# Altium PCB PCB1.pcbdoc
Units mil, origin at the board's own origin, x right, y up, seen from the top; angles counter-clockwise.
Board outline 2755.91 x 1968.5 mil, 2 copper layers (Top Layer, Bottom Layer), stack 62.206 mil thick; 33 components, 44 nets, 146 pads, 1 vias.
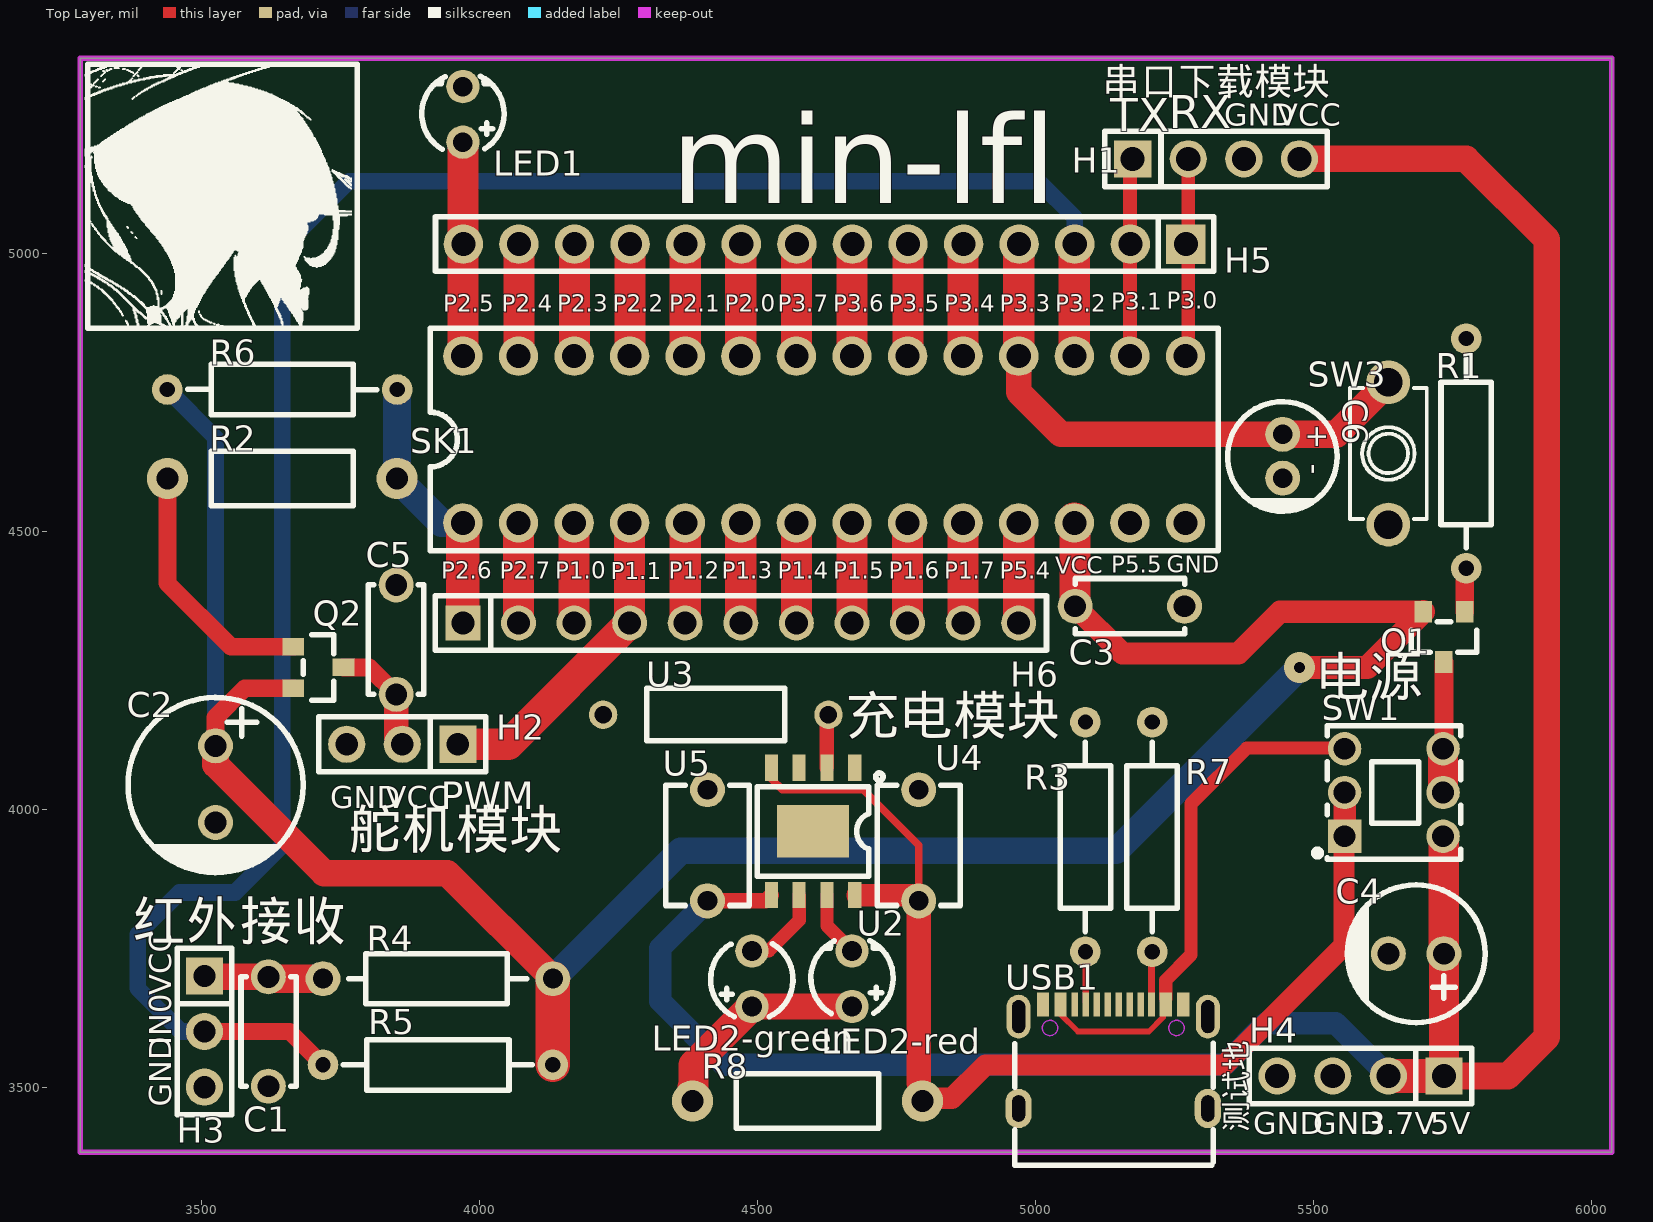
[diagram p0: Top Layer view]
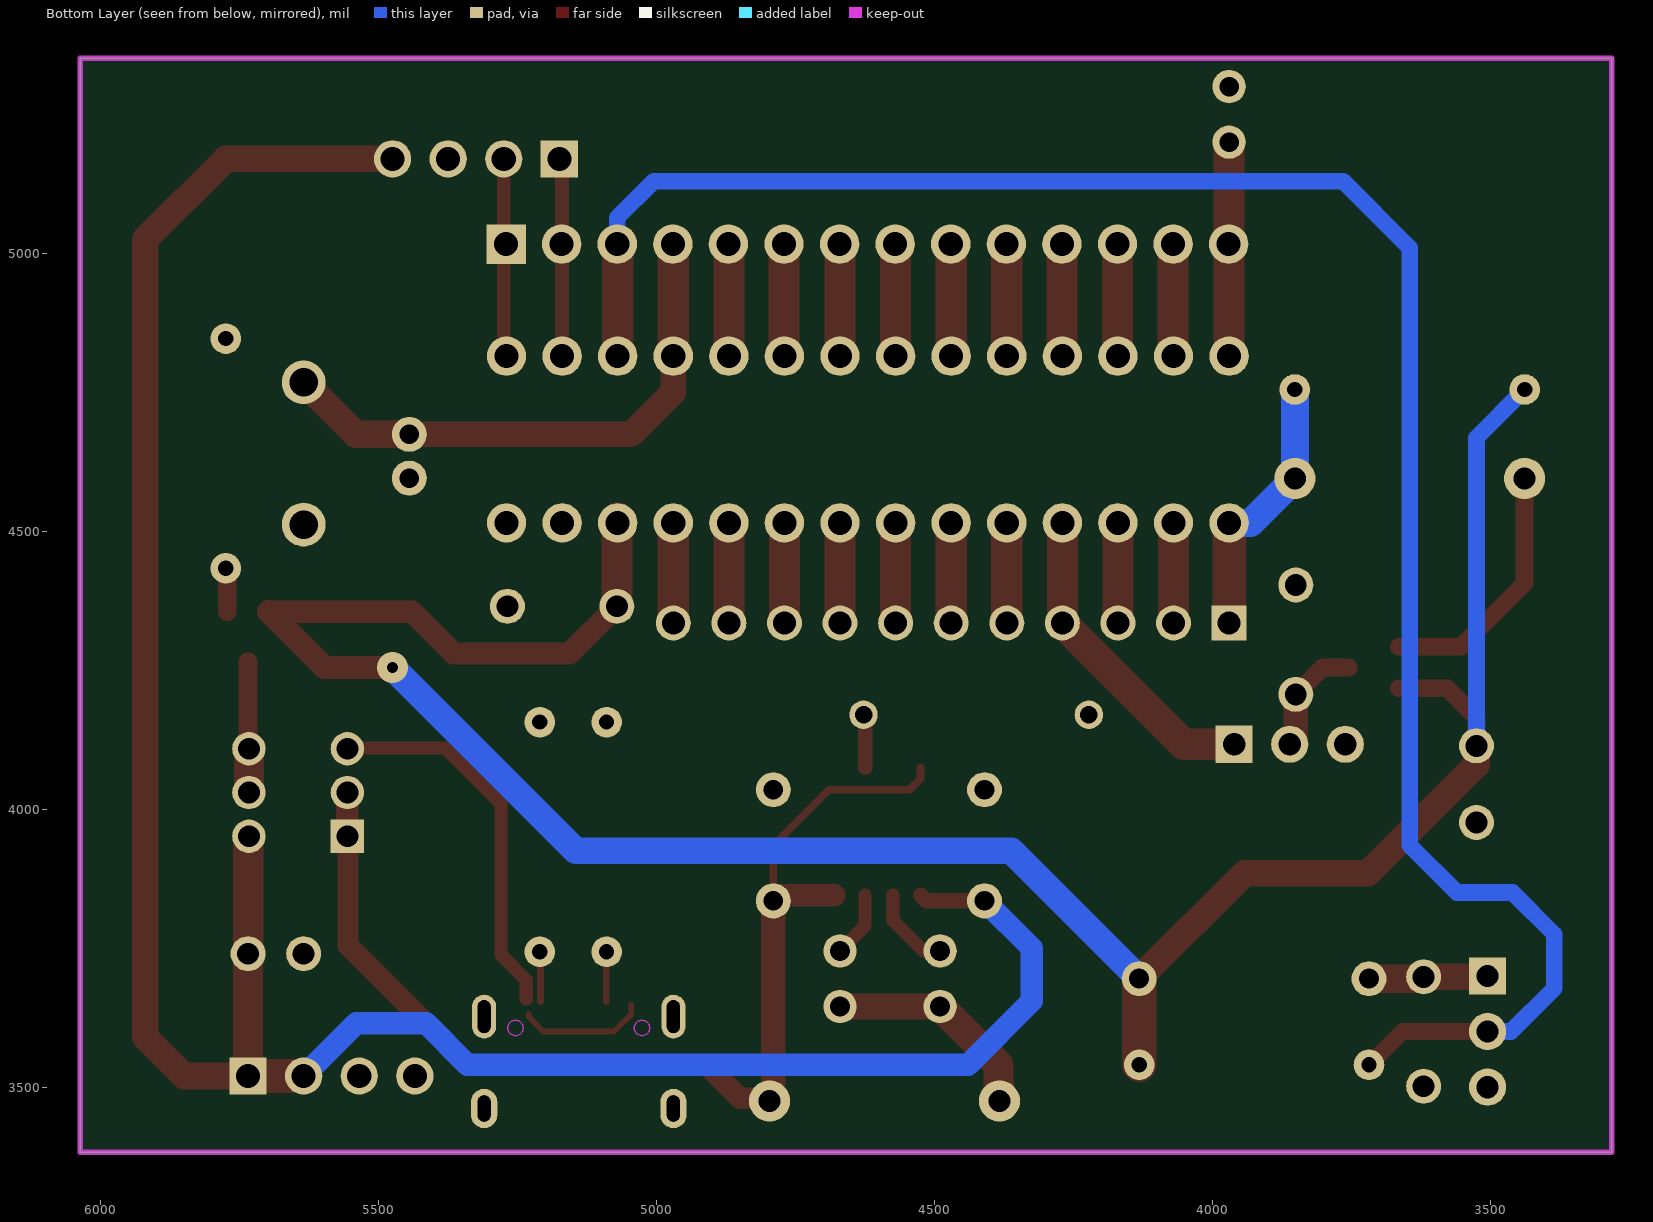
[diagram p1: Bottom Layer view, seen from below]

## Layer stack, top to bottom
Top Solder Mask Layer: solder mask 0.394, Dk 3.3
Top Layer: signal copper 1.379
Dielectric1: surface 59.449, FR4, Dk 4.5
Bottom Layer: signal copper 1.378
Bottom Solder Mask Layer: solder mask 0.394, Dk 3.3

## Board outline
3281.3,3382.8 3281.3,5351.3 6037.2,5351.3 6037.2,3382.8

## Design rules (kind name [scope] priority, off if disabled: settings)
BoardOutlineClearance copperThickness1oz [All] p0: genericclearance=10 ignorepadtopadclearanceinfootprint=FALSE except(0: Arc-SplitContinuation Track-SplitContinuation SMDPad-SplitContinuation THPad-SplitContinuation Via-SplitContinuation Fill-SplitContinuation Poly-SplitContinuation Region-SplitContinuation Text-SplitContinuation)
BoardOutlineClearance copperThickness2oz [All] p0: genericclearance=10 ignorepadtopadclearanceinfootprint=FALSE except(0: Arc-SplitContinuation Track-SplitContinuation SMDPad-SplitContinuation THPad-SplitContinuation Via-SplitContinuation Fill-SplitContinuation Poly-SplitContinuation Region-SplitContinuation Text-SplitContinuation)
BoardOutlineClearance otherClearance [All] p0: genericclearance=10 ignorepadtopadclearanceinfootprint=FALSE except(0: Arc-SplitContinuation Track-SplitContinuation SMDPad-SplitContinuation THPad-SplitContinuation Via-SplitContinuation Fill-SplitContinuation Poly-SplitContinuation Region-SplitContinuation Text-SplitContinuation)
Clearance copperThickness1oz [All] p1: gap=7 ignorepadtopadclearanceinfootprint=FALSE
Clearance copperThickness2oz [All] p1: gap=7 ignorepadtopadclearanceinfootprint=FALSE
Clearance otherClearance [All] p1: gap=7 ignorepadtopadclearanceinfootprint=FALSE
DiffPairsRouting differentialPair [All] p1: maxuncoupledlength=10 minlimit=6 maxlimit=Infinity mostfreqgap=6 toplayer_minwidth=5 toplayer_prefwidth=10 toplayer_maxwidth=100 bottomlayer_minwidth=5 bottomlayer_prefwidth=10 bottomlayer_maxwidth=100
PasteMaskExpansion pasteMaskExpansion [All] p1: expansion=0
PlaneConnect innerPlane [All] p1: planeconnectstyle=Relief reliefexpansion=20 reliefentries=4 reliefconductorwidth=10 reliefairgap=10
PolygonConnect copperRegion [All] p1: connectstyle=Relief reliefentries=4 reliefconductorwidth=10 polygonreliefangle="90 Angle" airgapwidth=10
PolygonConnect copperRegion1 [All] p1: connectstyle=Direct reliefentries=4 reliefconductorwidth=10 polygonreliefangle="90 Angle" airgapwidth=10
RoutingVias viaSize [All] p1: viastyle="Through Hole" holewidth=12.0078 minholewidth=11.811 maxholewidth=248.0314 width=12.0078 minwidth=11.811 maxwidth=248.0314
SolderMaskExpansion solderMaskExpansion [IsVia] p1: useseparateexpansions=TRUE expansion=-1000 expansionbottom=-1000
SolderMaskExpansion solderMaskExpansion [All] p2: useseparateexpansions=TRUE expansion=2 expansionbottom=2
Width copperThickness1oz [All] p1: maxlimit=100 minlimit=5 preferedwidth=10
Width copperThickness2oz [All] p1: maxlimit=100 minlimit=8 preferedwidth=10

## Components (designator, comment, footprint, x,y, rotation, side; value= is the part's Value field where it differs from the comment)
C1 "100nF" CAP-TH_L5.0-W2.5-P5.00-D1.0 3620,3600 r90 top
C2 "470uF" CAP-TH_BD8.0-P3.50-D0.6-FD_1 3525,4045 r270 top
C3 "100nF" CAP-TH_L5.0-W2.5-P5.00-D1.0 5170,4365 r180 top
C4 "47uF" CAP-TH_BD6.3-P2.50-D1.0-FD 5685,3740 r180 top
C5 "100nF" CAP-TH_L5.0-W2.5-P5.00-D1.0 3850,4305 r270 top
C6 "10uF" CAP-TH_BD5.0-P2.00-D0.5-FD-A 5445,4635 r270 top
H1 "PZ254V-11-04P" HDR-TH_4P-P2.54-V-M 5325,5170 r0 top
H2 "PZ254V-11-03P" HDR-TH_3P-P2.54-V-M_PZ254V-11-03P 3860.96,4116.74 r180 top
H3 "PZ254V-11-03P" HDR-TH_3P-P2.54-V-M_PZ254V-11-03P 3505,3600 r270 top
H4 "PZ254V-11-04P" HDR-TH_4P-P2.54-V-M 5585,3520 r180 top
H5 "PZ254-1-14-Z-8.5" HDR-TH_14P-P2.54-V-M 4620.76,5016.73 r180 top
H6 "PZ254V-11-11P" HDR-TH_11P-P2.54-V-M 4470,4335 r0 top
LED1 "XL-302SURD" LED-TH_BD3.8-P2.54-RD 3970,5250 r270 top
LED2-green "XL-302UGD" LED-TH_BD3.8-P2.54-FD_GREEN 4490,3695 r90 top
LED2-red "XL-302SURD" LED-TH_BD3.8-P2.54-RD 4670,3695 r270 top
Q1 "AO3401A" SOT-23_L2.9-W1.3-P1.90-LS2.4-BR 5735,4310 r90 top
Q2 "AO3401A" SOT-23_L2.9-W1.3-P1.90-LS2.4-BR 3710,4255 r180 top
R1 "4.7kΩ" RES-TH_BD2.3-L6.5-P10.50-D0.5 5775,4640 r270 top
R2 "1kΩ" RES-TH_BD2.5-L6.5-P10.50-D0.6 3645,4595 r180 top
R3 "5.1kΩ" RES-TH_BD2.3-L6.5-P10.50-D0.5 5090,3950 r270 top
R4 "100Ω" RES-TH_BD2.2-L6.5-P10.50-D0.6 3925,3695 r180 top
R5 "4.7kΩ" RES-TH_BD2.3-L6.5-P10.50-D0.5 3925,3540 r0 top
R6 "4.7kΩ" RES-TH_BD2.3-L6.5-P10.50-D0.5 3645,4755 r180 top
R7 "5.1kΩ" RES-TH_BD2.3-L6.5-P10.50-D0.5 5210,3950 r270 top
R8 "1kΩ" RES-TH_BD2.5-L6.5-P10.50-D0.6 4590,3475 r0 top
SK1 "IC-28P窄" DIP-28_L36.0-W10.2-P2.54-LS10.2-BL 4620,4665 r0 top
SW1 "5.8 ZSGT" SW-TH_5.8ZSGT 5645,4030 r270 top
SW3 "TC-1101T-C-B-B" KEY-TH_2P-L6.0-W3.5-P6.50 5635,4640 r90 top
U2 "TP4056" ESOP-8_L4.9-W3.9-P1.27-LS6.0-BL-EP 4600,3960 r180 top
U3 "1.2kΩ" RES-TH_BD2.4-L6.3-P10.30-D0.6 4425,4170 r0 top
U4 "10uF" CAP-TH_L5.5-W3.8-P5.08-D0.5 4790,3935 r270 top
U5 "10uF" CAP-TH_L5.5-W3.8-P5.08-D0.5 4410,3935 r270 top
USB1 "TYPE-C 16PIN 2MD(073)" USB-C-SMD_TYPE-C-6PIN-2MD-073 5140,3555 r0 top

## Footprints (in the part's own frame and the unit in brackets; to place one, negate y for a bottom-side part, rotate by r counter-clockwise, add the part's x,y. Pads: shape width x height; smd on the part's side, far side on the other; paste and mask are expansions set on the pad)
CAP-TH_BD5.0-P2.00-D0.5-FD-A [mm]
  round 1.6 hole 0.9 paste+0 mask+0.05: 1(-1,0) 2(1,0)
  silkscreen extent -2.49,-2.52 2.6,2.49
CAP-TH_BD6.3-P2.50-D1.0-FD [mm]
  round 1.6 hole 1: 1(-1.27,0) 2(1.27,0)
  silkscreen extent -3.15,-3.15 3.17,3.15
CAP-TH_BD8.0-P3.50-D0.6-FD_1 [mm]
  round 1.6 hole 1: 1(-1.75,0) 2(1.75,0)
  silkscreen extent -3.96,-4 4.04,4
CAP-TH_L5.0-W2.5-P5.00-D1.0 [mm]
  round 1.6 hole 1: 1(-2.5,0) 2(2.5,0)
  silkscreen extent -2.5,-1.27 2.5,1.25
CAP-TH_L5.5-W3.8-P5.08-D0.5 [mm]
  round 1.6 hole 0.9: 1(-2.54,0) 2(2.54,0)
  silkscreen extent -2.75,-1.9 2.75,1.9
DIP-28_L36.0-W10.2-P2.54-LS10.2-BL [mm]
  round 1.8 hole 1.1: 1(-16.51,-3.81) 2(-16.51,3.81) 3(-13.97,-3.81) 4(-13.97,3.81) 5(-11.43,-3.81) 6(-11.43,3.81) 7(-8.89,-3.81) 8(-8.89,3.81) 9(-6.35,-3.81) 10(-6.35,3.81) 11(-3.81,-3.81) 12(-3.81,3.81) 13(-1.27,-3.81) 14(-1.27,3.81) 15(1.27,-3.81) 16(1.27,3.81) 17(3.81,-3.81) 18(3.81,3.81) 19(6.35,-3.81) 20(6.35,3.81) 21(8.89,-3.81) 22(8.89,3.81) 23(11.43,-3.81) 24(11.43,3.81) 25(13.97,-3.81) 26(13.97,3.81) 27(16.51,-3.81) 28(16.51,3.81)
  silkscreen extent -18,-5.08 18,5.08
ESOP-8_L4.9-W3.9-P1.27-LS6.0-BL-EP [mm]
  rect 0.6x1.2 smd: 1(-1.905,-2.908) 2(-0.635,-2.908) 3(0.635,-2.908) 4(1.905,-2.908) 5(1.905,2.908) 6(0.635,2.908) 7(-0.635,2.908) 8(-1.905,2.908)
  rect 3.3x2.4 smd: 9(0,0)
  silkscreen extent -3.2,-2.67 2.55,2.05
HDR-TH_3P-P2.54-V-M_PZ254V-11-03P [mm]
  rect 1.7x1.7 hole 1.02: 1(-2.54,0)
  round 1.7 hole 1.02: 2(0,0) 3(2.54,0)
  silkscreen extent -3.81,-1.25 3.81,1.25
HDR-TH_4P-P2.54-V-M [mm]
  rect 1.7x1.7 hole 1.1: 1(-3.81,0)
  round 1.7 hole 1.1: 2(-1.27,0) 3(1.27,0) 4(3.81,0)
  silkscreen extent -5.08,-1.27 5.08,1.27
HDR-TH_11P-P2.54-V-M [mm]
  rect 1.6x1.6 hole 1.05: 1(-12.7,0)
  round 1.6 hole 1.05: 2(-10.16,0) 3(-7.62,0) 4(-5.08,0) 5(-2.54,0) 6(0,0) 7(2.54,0) 8(5.08,0) 9(7.62,0) 10(10.16,0) 11(12.7,0)
  silkscreen extent -13.97,-1.25 13.97,1.25
HDR-TH_14P-P2.54-V-M [mm]
  rect 1.8x1.8 hole 1.1: 1(-16.51,0)
  round 1.8 hole 1.1: 2(-13.97,0) 3(-11.43,0) 4(-8.89,0) 5(-6.35,0) 6(-3.81,0) 7(-1.27,0) 8(1.27,0) 9(3.81,0) 10(6.35,0) 11(8.89,0) 12(11.43,0) 13(13.97,0) 14(16.51,0)
  silkscreen extent -17.78,-1.25 17.78,1.25
KEY-TH_2P-L6.0-W3.5-P6.50 [mm]
  round 2 hole 1.3: 1(-3.25,0) 2(3.25,0)
  silkscreen extent -3,-1.75 3,1.75
LED-TH_BD3.8-P2.54-FD_GREEN [mil]
  round 60 hole 35.43: 1(-50,0) 2(50,0)
  silkscreen extent -68,-74 63,74
LED-TH_BD3.8-P2.54-RD [mil]
  round 60 hole 35.43: 1(-50,0) 2(50,0)
  silkscreen extent -68,-74 63,74
RES-TH_BD2.2-L6.5-P10.50-D0.6 [mm]
  round 1.6 hole 0.914: 1(-5.25,0) 2(5.25,0)
  silkscreen extent -4.06,-1.14 4.06,1.14
RES-TH_BD2.3-L6.5-P10.50-D0.5 [mm]
  round 1.4 hole 0.7: 1(-5.25,0) 2(5.25,0)
  silkscreen extent -4.32,-1.15 4.32,1.15
RES-TH_BD2.4-L6.3-P10.30-D0.6 [mm]
  round 1.3 hole 0.8: 1(-5.15,0) 2(5.15,0)
  silkscreen extent -3.15,-1.2 3.15,1.2
RES-TH_BD2.5-L6.5-P10.50-D0.6 [mil]
  round 74 hole 39.37: 1(-206.69,0) 2(206.69,0)
  silkscreen extent -128,-49 128,49
SOT-23_L2.9-W1.3-P1.90-LS2.4-BR [mm]
  rect 1x0.8 smd: 1(1.15,-0.95) 2(1.15,0.95) 3(-1.15,0)
  silkscreen extent -0.7,-1.5 0.7,1.5
SW-TH_5.8ZSGT [mm]
  rect 1.524x1.524 hole 1: 1(2,-2.25)
  round 1.524 hole 1: 2(0,-2.25) 3(-2,-2.25) 4(2,2.25) 5(0,2.25) 6(-2,2.25)
  silkscreen extent -3.05,-3.64 3.05,3.05
USB-C-SMD_TYPE-C-6PIN-2MD-073 [mm]
  rect 0.55x1.1 smd paste-100 mask+0.05: 1(-3.2,2.375) 2(-2.4,2.375) 11(2.4,2.375) 12(3.2,2.375)
  rect 0.3x1.1 smd paste-100 mask+0.05: 3(-1.75,2.375) 4(-1.25,2.375) 5(-0.75,2.375) 6(-0.25,2.375) 7(0.25,2.375) 8(0.75,2.375) 9(1.25,2.375) 10(1.75,2.375)
  oval 1.2x1.8 hole 0.6 slot 1.2 at 90 deg paste+0 mask+0.05: 13(-4.325,-2.375) 14(4.325,-2.375)
  oval 1.1x2 hole 0.6 slot 1.5 at 90 deg paste+0 mask+0.05: 13(-4.325,1.825) 14(4.325,1.825)
  Board Outline Layer circle w0.003: c-2.89,1.305 r0.35
  Board Outline Layer circle w0.003: c2.89,1.305 r0.35
  Board Outline Layer region: -2.54,1.305 -2.575,1.153 -2.672,1.031 -2.812,0.964 -2.968,0.964 -3.108,1.031 -3.205,1.153 -3.24,1.305 -3.24,1.305 -3.205,1.457 -3.108,1.579 -2.968,1.646 -2.812,1.646 -2.672,1.579 -2.575,1.457 -2.54,1.305
  Board Outline Layer region: -2.54,1.305 -2.575,1.153 -2.672,1.031 -2.812,0.964 -2.968,0.964 -3.108,1.031 -3.205,1.153 -3.24,1.305 -3.24,1.305 -3.205,1.457 -3.108,1.579 -2.968,1.646 -2.812,1.646 -2.672,1.579 -2.575,1.457 -2.54,1.305
  Board Outline Layer region: 3.24,1.305 3.205,1.153 3.108,1.031 2.968,0.964 2.812,0.964 2.672,1.031 2.575,1.153 2.54,1.305 2.54,1.305 2.575,1.457 2.672,1.579 2.812,1.646 2.968,1.646 3.108,1.579 3.205,1.457 3.24,1.305
  Board Outline Layer region: 3.24,1.305 3.205,1.153 3.108,1.031 2.968,0.964 2.812,0.964 2.672,1.031 2.575,1.153 2.54,1.305 2.54,1.305 2.575,1.457 2.672,1.579 2.812,1.646 2.968,1.646 3.108,1.579 3.205,1.457 3.24,1.305
  silkscreen extent -4.5,-4.97 4.57,0.6

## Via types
v1: diameter 56, hole 20, Top Layer to Bottom Layer, 1 vias

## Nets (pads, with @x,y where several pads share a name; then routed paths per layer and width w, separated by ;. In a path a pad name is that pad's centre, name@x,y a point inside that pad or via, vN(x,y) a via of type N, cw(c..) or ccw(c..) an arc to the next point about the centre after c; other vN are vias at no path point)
$1N91: C1.2 H3.1 R4.2 | length 215.4
  Top Layer w48: H3.1 3506.57,3698.43 C1.2
  Top Layer w52: C1.2 3623.43,3695 R4.2
$1N196: C5.2 H2.2 Q2.3 | length 209.2
  Top Layer w32: Q2.3 3801.57,4255 C5.2
  Top Layer w44: C5.2 3850,4127.7 H2.2
$1N197: Q2.1 R2.2 | length 462.1
  Top Layer w32: R2.2 3438.31,4406.69 3552.6,4292.4 Q2.1
$1N206: Q1.3 SW1.5 SW1.6 | length 235.3
  Top Layer w34: SW1.6 5735,4110.15 Q1.3
  Top Layer w54: SW1.5 SW1.6
$1N219: Q1.1 R1.2 | length 79.1
  Top Layer w34: Q1.1 5772.4,4430.71 R1.2
$1N223: U2.2 U3.2 | length 96.6
  Top Layer w26: U2.2 4625,4167.24 U3.2
$1N241: R7.2 USB1.10 | length 80.3
  Top Layer w12: USB1.10@5208.9,3653.51 5208.9,3732.22 R7.2@5210,3733.31
$1N242: R3.2 USB1.4 | length 80.1
  Top Layer w12: R3.2@5090,3733.31 5090.8,3732.51 USB1.4@5090.8,3653.51
$1N244: LED2-red.1 U2.7 | length 119.1
  Top Layer w24: U2.7 4625,3790 LED2-red.1
$1N245: LED2-green.2 U2.6 | length 153.3
  Top Layer w24: LED2-green.2 4520,3745 4575,3800 U2.6
$1N246: LED2-green.1 LED2-red.2 R8.1 | length 369.2
  Top Layer w46: LED2-green.1 LED2-red.2
  Top Layer w54: R8.1@4383.31,3500 4385,3501.69 4385,3540 LED2-green.1
BAT-VCC: C4.1 H1.4 H4.1 H4.2 SW1.4 U2.5 U5.2 | length 4448.5
  Top Layer w28: U5.2 4514.5,3835 U2.5
  Top Layer w48: H1.4 5775,5170 5920,5025 5920,3590 5850,3520 H4.1
  Top Layer w54: H4.1 C4.1
  Top Layer w55: SW1.4 5735,3949.85 C4.1
  Top Layer w62: H4.2 H4.1
  Bottom Layer w40: U5.2 4325,3750 4325,3655 4440,3540 5340,3540 5415,3615 5540,3615 H4.2
GND: C1.1 C2.2 C3.1 C4.2 C5.1 C6.2 H1.3 H2.3 H3.3 H4.3 H4.4 LED1.1 R1.1 R3.1 R7.1 SK1.27 SW3.1 U2.1 U2.3 U2.9 U3.1 U4.1 U5.1 USB1.1 USB1.12 USB1.13 USB1.14
P1.0: H6.3 SK1.5 | length 185
  Top Layer w56: H6.3 SK1.5@4170,4520
P1.1/PWM: H2.1 H6.4 SK1.7 | length 584.4
  Top Layer w56: H2.1 4051.74,4116.74 H6.4 SK1.7@4270,4520
P1.2: H6.5 SK1.9 | length 185
  Top Layer w56: H6.5 SK1.9@4370,4520
P1.3: H6.6 SK1.11 | length 185
  Top Layer w56: H6.6 SK1.11@4470,4520
P1.4: H6.7 SK1.13 | length 185
  Top Layer w56: H6.7 SK1.13@4570,4520
P1.5: H6.8 SK1.15 | length 185
  Top Layer w56: H6.8 SK1.15@4670,4520
P1.6: H6.9 SK1.17 | length 185
  Top Layer w56: H6.9 SK1.17@4770,4520
P1.7: H6.10 SK1.19 | length 185
  Top Layer w56: H6.10 SK1.19@4870,4520
P2.0: H5.9 SK1.12 | length 197
  Top Layer w50: H5.9@4470,5015.97 H5.9
  Top Layer w56: SK1.12@4470,4820 H5.9@4470,5015.97
P2.1: H5.10 SK1.10 | length 197
  Top Layer w50: H5.10@4370,5015.97 H5.10
  Top Layer w56: SK1.10@4370,4820 H5.10@4370,5015.97
P2.2: H5.11 SK1.8 | length 197
  Top Layer w50: SK1.8@4270,4820 SK1.8@4270.76,4820.76
  Top Layer w56: SK1.8@4270.76,4820.76 H5.11
P2.3: H5.12 SK1.6 | length 197
  Top Layer w50: SK1.6@4170,4820 SK1.6@4170.76,4820.76
  Top Layer w56: SK1.6@4170.76,4820.76 H5.12
P2.4: H5.13 SK1.4 | length 197
  Top Layer w50: SK1.4@4070,4820 SK1.4@4070.76,4820.76
  Top Layer w56: SK1.4@4070.76,4820.76 H5.13
P2.5/LED1: H5.14 LED1.2 SK1.2 | length 380
  Top Layer w56: SK1.2@3970,4820 LED1.2
P2.6/SG90: H6.1 R2.1 R6.1 SK1.1 | length 491.4
  Top Layer w60: H6.1 SK1.1
  Bottom Layer w50: R6.1 R2.1 3931.69,4515 SK1.1
P2.7: H6.2 SK1.3 | length 185
  Top Layer w56: H6.2 SK1.3@4070,4520
P3.0/RX: H1.2 H5.1 SK1.28 | length 352.1
  Top Layer w25: SK1.28@5270,4820 5275,4825 H1.2
P3.1/TX: H1.1 H5.2 SK1.26 | length 352.1
  Top Layer w25: SK1.26@5170,4820 5170,5165 H1.1
P3.2/IN0: H3.2 H5.3 R5.1 SK1.24 | length 3636.3
  Top Layer w30: H3.2 3658.31,3600 R5.1
  Top Layer w50: H5.3@5070,5015.97 H5.3
  Top Layer w56: SK1.24@5070,4820 H5.3@5070,5015.97
  Bottom Layer w30: H3.2 3462.57,3600 3385,3677.57 3385,3775 3460,3850 3560,3850 3645,3935 3645,5010 3765,5130 5005,5130 5070.76,5064.24 H5.3
P3.3/KEY: C6.1 H5.4 SK1.22 SW3.2 | length 997.1
  Top Layer w46: SK1.22 4970,4750 5045.63,4674.37 C6.1
  Top Layer w50: H5.4@4970,5015.97 H5.4 ; C6.1 5541.42,4674.37 SW3.2
  Top Layer w56: SK1.22@4970,4820 H5.4@4970,5015.97
P3.4: H5.5 SK1.20 | length 197
  Top Layer w50: H5.5@4870,5015.97 H5.5
  Top Layer w56: SK1.20@4870,4820 H5.5@4870,5015.97
P3.5: H5.6 SK1.18 | length 197
  Top Layer w50: SK1.18@4770,4820 SK1.18@4770.76,4820.76
  Top Layer w56: SK1.18@4770.76,4820.76 H5.6
P3.6: H5.7 SK1.16 | length 197
  Top Layer w50: H5.7@4670,5015.97 H5.7
  Top Layer w56: SK1.16@4670,4820 H5.7@4670,5015.97
P3.7: H5.8 SK1.14 | length 197
  Top Layer w50: H5.8@4570,5015.97 H5.8
  Top Layer w56: SK1.14@4570,4820 H5.8@4570,5015.97
P5.4: H6.11 SK1.21 | length 185
  Top Layer w56: H6.11 SK1.21@4970,4520
P5.5: SK1.25
TYPEC-SW-L: SW1.3 | length 231.8
  Top Layer w10: 5045.52,3648.51 5045.52,3631 5076.52,3600 5204.15,3600 5230,3625.85 5230,3632.07
typec-sw-L: USB1.2 USB1.11 | length 686.8
  Top Layer w24: USB1.11@5234.49,3658.51 5234.49,3692.45 5280,3737.95 5280,4010 5380,4110 5555,4110
typec-sw-R: R8.2 SW1.1 SW1.2 U2.4 U2.8 U4.2 | length 1070.3
  Top Layer w14: U2.4@4525,4055 U2.4
  Top Layer w38: R8.2@4816.69,3480 4850,3480 4910,3540 5340,3540 5555,3755 SW1.1@5555,3950
  Top Layer w40: U4.2@4787.5,3837.5 U4.2
TYPEC-SW-R:  | length 876.6
  Top Layer w14: 4525,4055 4545,4035 4690,4035 4790,3935 4790,3860
  Top Layer w40: 4680,3845 4780,3845 ; 5556.42,3971.42 5556.42,4030
  Top Layer w44: 4790,3506.69 4790,3835
VCC: C2.1 C3.2 Q1.2 Q2.2 R4.1 R5.2 R6.2 SK1.23 | length 4532.1
  Top Layer w32: C2.1 3525,4165 3577.6,4217.6 Q2.2
  Top Layer w40: C3.2 5156.57,4280 5365,4280 5440.27,4355.27 Q1.2
  Top Layer w42: v1(5475,4255) 5597.32,4255 Q1.2
  Top Layer w48: C2.1 3525,4080 3720,3885 3941.7,3885 R4.1
  Top Layer w56: C3.2 SK1.23@5071.57,4518.43
  Top Layer w62: R5.2 R4.1
  Top Layer w64: SK1.23@5070,4520 SK1.23@5071.57,4518.43
  Bottom Layer w30: R6.2 3525,4668.31 C2.1
  Bottom Layer w48: R4.1 4361.69,3925 5145,3925 v1(5475,4255)
pads on no net: USB1.3 USB1.5 USB1.6 USB1.7 USB1.8 USB1.9

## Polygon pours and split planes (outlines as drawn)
GND on Bottom Layer (solid, remove dead copper, pour order 4): 3080,5485 6510,5485 6510,3000 3080,3000
GND on Top Layer (solid, remove dead copper, pour order 2): 3000,5415 6210,5415 6210,3160 3000,3160
GND on Top Layer (solid, remove dead copper, pour order 0): 3125,5395 6125,5395 6125,3340 3125,3340

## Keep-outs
Board Outline Layer:
  the board outline again, w10

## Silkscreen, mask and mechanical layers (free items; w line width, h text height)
Top Silkscreen Layer:
  drawing of 85 lines, arcs and shapes, not listed
  text "串口下载模块" at 5120,5285 h50
  text "GND" at 5340,5230 h40
  text "VCC" at 5435,5230 h40
  text "RX" at 5240,5225 h60
  text "TX" at 5135,5220 h60
  text "min-lfl" at 4345,5090 h160
  text "P3.0" at 5236.1,4900 h30
  text "P3.1" at 5136.1,4898.25 h30
  text "P2.5" at 3935,4895 h30
  text "P2.4" at 4040,4895 h30
  text "P2.3" at 4140,4895 h30
  text "P2.2" at 4240,4895 h30
  text "P2.1" at 4341.1,4895 h30
  text "P2.0" at 4441.1,4895 h30
  text "P3.7" at 4536.1,4895 h30
  text "P3.6" at 4636.1,4895 h30
  text "P3.5" at 4736.1,4895 h30
  text "P3.4" at 4836.1,4895 h30
  text "P3.3" at 4936.1,4895 h30
  text "P3.2" at 5036.1,4895.14 h30
  text "P5.5" at 5136.1,4425 h30
  text "GND" at 5236.1,4425.35 h30
  text "VCC" at 5036.1,4423.28 h30
  text "P2.6" at 3931.1,4415 h30
  text "P2.7" at 4036.1,4415 h30
  text "P1.0" at 4136.1,4415 h30
  text "P1.2" at 4340,4415 h30
  text "P1.3" at 4436.1,4415 h30
  text "P1.4" at 4536.1,4415 h30
  text "P1.5" at 4636.1,4415 h30
  text "P1.6" at 4736.1,4415 h30
  text "P1.7" at 4836.1,4415 h30
  text "P5.4" at 4936.1,4415 h30
  text "P1.1" at 4236.1,4413.96 h30
  text "电源" at 5505,4205 h70
  text "充电模块" at 4660,4135 h70
  text "GND" at 3730.96,4001.74 h40
  text "VCC" at 3830.96,4001.74 h40
  text "PWM" at 3930,4000 h50
  text "舵机模块" at 3765,3930 h70
  text "红外接收" at 3375,3765 h70
  text "VCC" at 3445,3665 h40 r90
  text "IN0" at 3445,3575 h40 r90
  text "GND" at 3445,3465 h40 r90
  text "测试地" at 5380,3420 h40 r90
  text "GND" at 5391.7,3415 h40
  text "GND" at 5500,3415 h40
  text "3.7V" at 5595,3415 h40
  text "5V" at 5710,3415 h40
